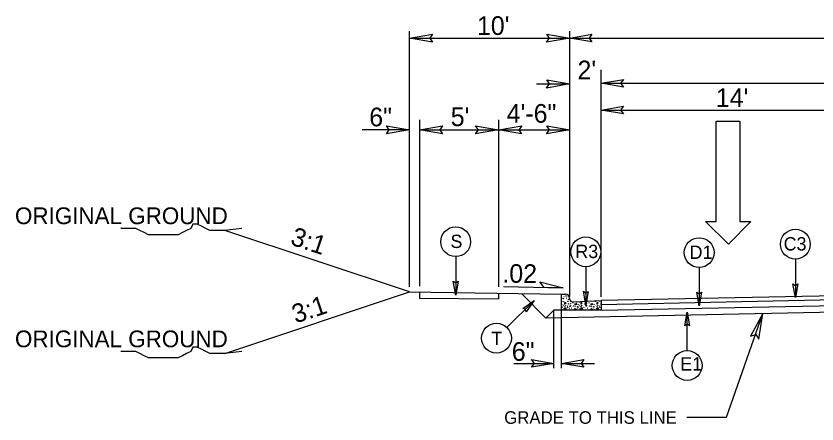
# Model space of a CAD drawing. Extents: x 958711 to 962106, y 831169 to 840840.
# Drawn here: x 960909.4 to 961244.1, y 838613.5 to 838784 of the extents above; entities that cross this region are included whole.
import ezdxf

# ---------------------------------------------------------------- set-up
doc = ezdxf.new("R2010")
doc.units = 0
for name, color, linetype in [('Old_Level_1', 7, 'Continuous'), ('Old_Level_11', 7, 'Continuous'), ('Old_Level_21', 7, 'Continuous'), ('Old_Level_3', 7, 'Continuous'), ('Prop Dimension Text', 7, 'Continuous'), ('Prop Lane Arrow CELL', 7, 'Continuous'), ('Typical ID Circle CELL', 7, 'Continuous'), ('Typical Terminator CELL', 7, 'Continuous'), ('Typical Text ID Circle CELL', 7, 'Continuous')]:
    doc.layers.add(name, color=color, linetype=linetype)

# ---------------------------------------------------------------- blocks, each defined once
blk = doc.blocks.new('Lane Arrow Through')
at = {"layer": 'Prop Lane Arrow CELL'}
for p, q in [((-3.15, 1.6), (-3.15, 3.1)), ((-3.15, 3.1), (0, 0)), ((-17.15, 1.6), (-3.15, 1.6)), ((-17.15, -1.7), (-17.15, 1.6)), ((0, 0), (-3.15, -3.2)), ((-3.15, -1.7), (-17.15, -1.7)), ((-3.15, -3.2), (-3.15, -1.7))]:
    blk.add_line(p, q, dxfattribs=at)

msp = doc.modelspace()

# ---------------------------------------------------------------- linework, layer by layer
at = {"layer": 'Old_Level_1'}
for p, q in [((961073.8, 838670.85), (961073.8, 838777.7)), ((961140.72, 838666.82), (961140.72, 838777.74)), ((961073.8, 838774.8), (961140.72, 838774.8)), ((961140.72, 838774.8), (961707.16, 838774.8)), ((961153.92, 838666.59), (961153.92, 838761.56)), ((961126.89, 838755.64), (961140.72, 838755.64)), ((961153.92, 838755.91), (961354.09, 838755.91)), ((961153.92, 838744.66), (961260.61, 838744.66)), ((961077.98, 838740.63), (961077.98, 838671.06)), ((961111, 838740.63), (961111, 838670.84)), ((961073.8, 838736.46), (961054.01, 838736.46)), ((961077.98, 838736.46), (961111, 838736.46)), ((961111, 838736.46), (961140.72, 838736.46)), ((961073.8, 838668.67), (960996.61, 838694.4)), ((961113.05, 838670.94), (961138.02, 838670.44)), ((960996.61, 838642.94), (961073.8, 838668.67)), ((961073.8, 838668.67), (961137.64, 838667.73)), ((961077.98, 838668.61), (961077.98, 838666.15)), ((961111, 838668.12), (961111, 838665.82)), ((961130.8, 838657.78), (961120.69, 838667.9)), ((961354.09, 838669.12), (961153.92, 838665.08)), ((961077.98, 838666.15), (961111, 838665.82)), ((961259.53, 838665.49), (961153.92, 838663.35)), ((961259.53, 838663.06), (961153.92, 838660.92)), ((961134.05, 838661.03), (961130.8, 838657.78)), ((961259.53, 838660.39), (961130.8, 838657.78)), ((961137.35, 838661.09), (961134.05, 838661.03)), ((961134.05, 838636.87), (961134.05, 838660.83)), ((961137.35, 838636.87), (961137.35, 838660.83)), ((961206.28, 838616.3), (961221.49, 838659.62)), ((961117.45, 838638.83), (961134.05, 838638.83)), ((961137.35, 838638.83), (961151.08, 838638.83)), ((961189.66, 838616.3), (961206.28, 838616.3))]:
    msp.add_line(p, q, dxfattribs=at)
at = {"layer": 'Old_Level_11'}
for p, q in [((961130.02, 838670.6), (961128.29, 838672.85)), ((961128.29, 838672.85), (961138.02, 838670.44)), ((961138.02, 838670.44), (961130.02, 838670.6))]:
    msp.add_line(p, q, dxfattribs=at)
for points in [[(961083.41, 838773.14), (961073.8, 838774.8), (961083.46, 838776.51), (961082.24, 838774.8)], [(961131.11, 838776.45), (961140.72, 838774.8), (961131.05, 838773.08), (961132.28, 838774.8)], [(961131.11, 838757.3), (961140.72, 838755.64), (961131.05, 838753.92), (961132.28, 838755.64)], [(961064.19, 838738.12), (961073.8, 838736.46), (961064.13, 838734.74), (961065.36, 838736.46)], [(961087.59, 838734.8), (961077.98, 838736.46), (961087.64, 838738.17), (961086.42, 838736.46)], [(961101.39, 838738.12), (961111, 838736.46), (961101.33, 838734.74), (961102.56, 838736.46)], [(961120.61, 838734.8), (961111, 838736.46), (961120.66, 838738.17), (961119.44, 838736.46)], [(961131.11, 838738.12), (961140.72, 838736.46), (961131.05, 838734.74), (961132.28, 838736.46)], [(961219.8, 838649.02), (961221.49, 838659.62), (961216.28, 838650.16), (961218.48, 838650.84)]]:
    msp.add_lwpolyline(points, close=True, dxfattribs=at)
at = {"layer": 'Old_Level_21'}
for points in [[(961003.71, 838695.28), (960996.61, 838694.4), (960994.84, 838694.4), (960992.18, 838694.4), (960990.4, 838694.4), (960988.63, 838695.28), (960986.85, 838696.18), (960985.08, 838697.06), (960983.31, 838697.06), (960982.41, 838695.28), (960980.65, 838694.4), (960978.87, 838693.51), (960977.1, 838692.63), (960975.32, 838692.63), (960973.55, 838692.63), (960971.78, 838692.63), (960970.01, 838692.63), (960968.23, 838692.63), (960966.46, 838692.63), (960964.68, 838692.63), (960962.91, 838693.51), (960961.14, 838694.4), (960959.37, 838695.28), (960956.7, 838695.28), (960954.93, 838695.28), (960953.15, 838695.28)], [(961003.71, 838643.82), (960996.61, 838642.94), (960994.84, 838642.94), (960992.18, 838642.94), (960990.4, 838642.94), (960988.63, 838643.82), (960986.85, 838644.72), (960985.08, 838645.6), (960983.31, 838645.6), (960982.41, 838643.82), (960980.65, 838642.94), (960978.87, 838642.04), (960977.1, 838641.17), (960975.32, 838641.17), (960973.55, 838641.17), (960971.78, 838641.17), (960970.01, 838641.17), (960968.23, 838641.17), (960966.46, 838641.17), (960964.68, 838641.17), (960962.91, 838642.04), (960961.14, 838642.94), (960959.37, 838643.82), (960956.7, 838643.82), (960954.93, 838643.82), (960953.15, 838643.82)]]:
    msp.add_lwpolyline(points, dxfattribs=at)
at = {"layer": 'Old_Level_3'}
for p, q in [((961137.35, 838664.41), (961137.35, 838667.44)), ((961137.64, 838667.73), (961139.01, 838667.73)), ((961137.35, 838661.09), (961137.35, 838664.41)), ((961138.62, 838664.18), (961138.62, 838663.6)), ((961139.21, 838664.15), (961138.62, 838664.18)), ((961138.62, 838663.6), (961139.21, 838664.15)), ((961140.8, 838665.68), (961140.69, 838665.54)), ((961140.69, 838665.54), (961140.84, 838665.57)), ((961142.38, 838664.5), (961153.92, 838665.08)), ((961142.38, 838664.5), (961142.38, 838664.5)), ((961142.84, 838663.77), (961142.94, 838663.29)), ((961143.67, 838663.54), (961142.84, 838663.77)), ((961142.94, 838663.29), (961143.67, 838663.54)), ((961145.35, 838664.18), (961145.35, 838663.6)), ((961145.94, 838664.15), (961145.35, 838664.18)), ((961145.35, 838663.6), (961145.94, 838664.15)), ((961149.57, 838663.77), (961149.67, 838663.29)), ((961150.4, 838663.54), (961149.57, 838663.77)), ((961149.67, 838663.29), (961150.4, 838663.54)), ((961152.09, 838664.18), (961152.09, 838663.6)), ((961152.67, 838664.15), (961152.09, 838664.18)), ((961152.09, 838663.6), (961152.67, 838664.15)), ((961153.92, 838665.08), (961153.92, 838661.09)), ((961153.92, 838661.09), (961137.35, 838661.09)), ((961138.54, 838661.48), (961139, 838662.13)), ((961139.17, 838661.51), (961138.54, 838661.48)), ((961139, 838662.13), (961139.17, 838661.51)), ((961142.65, 838661.21), (961142.99, 838661.82)), ((961143.55, 838661.42), (961142.65, 838661.21)), ((961142.99, 838661.82), (961143.55, 838661.42)), ((961145.27, 838661.48), (961145.73, 838662.13)), ((961145.91, 838661.51), (961145.27, 838661.48)), ((961145.73, 838662.13), (961145.91, 838661.51)), ((961149.38, 838661.21), (961149.72, 838661.82)), ((961150.28, 838661.42), (961149.38, 838661.21)), ((961149.72, 838661.82), (961150.28, 838661.42)), ((961151.99, 838661.48), (961152.45, 838662.13)), ((961152.64, 838661.51), (961151.99, 838661.48)), ((961152.45, 838662.13), (961152.64, 838661.51))]:
    msp.add_line(p, q, dxfattribs=at)
for centre in [(961138.32, 838666.64), (961139.18, 838667.01), (961140.29, 838666.89), (961137.41, 838666), (961137.5, 838663.41), (961138.05, 838664.61), (961138.17, 838665.9), (961138.2, 838663.01), (961138.97, 838663.1), (961139.34, 838666.09), (961139.98, 838664.8), (961140.26, 838663.69), (961140.32, 838665.59), (961140.97, 838662.95), (961141, 838663.75), (961141.09, 838664.76), (961142.07, 838664.15), (961143.52, 838664), (961144.23, 838663.41), (961144.93, 838663.01), (961145.7, 838663.1), (961146.99, 838663.69), (961147.7, 838662.95), (961147.73, 838663.75), (961148.8, 838664.15), (961150.25, 838664), (961150.96, 838663.41), (961151.5, 838664.61), (961151.66, 838663.01), (961152.42, 838663.1), (961153.44, 838664.8), (961153.72, 838663.69), (961137.53, 838661.23), (961137.61, 838662.34), (961138.05, 838661.48), (961138.72, 838662.56), (961139.77, 838662.77), (961139.92, 838662.22), (961140.72, 838661.76), (961140.87, 838662.68), (961141.4, 838661.91), (961142.35, 838662.8), (961143, 838662.53), (961143.95, 838662), (961144.04, 838662.53), (961144.26, 838661.23), (961144.34, 838662.34), (961144.77, 838661.48), (961145.45, 838662.56), (961146.5, 838662.77), (961146.65, 838662.22), (961147.45, 838661.76), (961147.6, 838662.68), (961148.13, 838661.91), (961149.08, 838662.8), (961149.73, 838662.53), (961150.68, 838662), (961150.77, 838662.53), (961150.99, 838661.23), (961151.07, 838662.34), (961151.5, 838661.48), (961152.18, 838662.56), (961153.22, 838662.77), (961153.38, 838662.22)]:
    msp.add_circle(centre, 0.0432, dxfattribs=at)
for centre, radius, start, end in [((961137.64, 838667.44), 0.287, 90, 180), ((961137.53, 838667.66), 0.0432, 259.6531, 10.3469), ((961139.01, 838666.07), 1.66, 1.0734, 90), ((961142.3, 838666.14), 1.64, 181.0734, 272.8624), ((961144.77, 838664.61), 0.0432, 167.7795, 17.938), ((961147.82, 838664.76), 0.0432, 169.8374, 15.8801), ((961137.31, 838662.53), 0.0432, 330.4173, 29.5827)]:
    msp.add_arc(centre, radius, start, end, dxfattribs=at)
at = {"layer": 'Typical ID Circle CELL'}
for p, q in [((961093.08, 838683.46), (961093.08, 838667.38)), ((961235.02, 838682.44), (961235.02, 838666.35)), ((961147.47, 838679.26), (961147.47, 838663.17)), ((961194.83, 838678.91), (961194.83, 838662.82)), ((961114.51, 838653.76), (961125.88, 838665.14)), ((961189.82, 838644.17), (961189.82, 838660.26))]:
    msp.add_line(p, q, dxfattribs=at)
for centre in [(961093.08, 838689.69), (961235.02, 838688.66), (961147.47, 838685.48), (961194.83, 838685.13), (961110.11, 838649.36), (961189.82, 838637.95)]:
    msp.add_circle(centre, 6.23, dxfattribs=at)
at = {"layer": 'Typical Terminator CELL'}
for points in [[(961149.94, 838773.21), (961140.72, 838774.8), (961149.99, 838776.44), (961148.81, 838774.8)], [(961163.15, 838754.32), (961153.92, 838755.91), (961163.2, 838757.55), (961162.02, 838755.91)], [(961163.15, 838743.08), (961153.92, 838744.66), (961163.2, 838746.3), (961162.02, 838744.66)], [(961094.07, 838673.14), (961093.08, 838667.38), (961092.06, 838673.17), (961093.08, 838672.44)], [(961236.02, 838672.11), (961235.02, 838666.35), (961234, 838672.14), (961235.02, 838671.41)], [(961148.47, 838668.94), (961147.47, 838663.17), (961146.45, 838668.97), (961147.47, 838668.23)], [(961195.82, 838668.59), (961194.83, 838662.82), (961193.81, 838668.62), (961194.83, 838667.88)], [(961121.11, 838661.76), (961125.88, 838665.14), (961122.51, 838660.31), (961122.31, 838661.56)], [(961188.83, 838654.5), (961189.82, 838660.26), (961190.84, 838654.46), (961189.82, 838655.2)], [(961124.83, 838640.42), (961134.05, 838638.83), (961124.77, 838637.19), (961125.95, 838638.83)], [(961146.57, 838637.24), (961137.35, 838638.83), (961146.62, 838640.47), (961145.45, 838638.83)]]:
    msp.add_lwpolyline(points, close=True, dxfattribs=at)

# ---------------------------------------------------------------- block references
at = {"layer": 'Old_Level_1', "xscale": 3, "yscale": 3, "rotation": -90.00000000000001}
msp.add_blockref('Lane Arrow Through', (961207.08, 838688.69), dxfattribs=at)

# ---------------------------------------------------------------- texts
at = {"layer": 'Old_Level_1'}
msp.add_text('GRADE TO THIS LINE', height=5.2473, dxfattribs=at).set_placement((961113.35, 838613.57))
at = {"layer": 'Old_Level_21'}
for p in [(960908.93, 838697.03), (960908.93, 838645.57)]:
    msp.add_text('ORIGINAL GROUND', height=7, dxfattribs=at).set_placement(p)
at = {"layer": 'Old_Level_3'}
for s, p in [("10'", (961101.97, 838776.12)), ("2'", (961143.99, 838757.59)), ('4\'-6"', (961114.39, 838739.43)), ('6"', (961056.96, 838737.93)), ("5'", (961091, 838738.02))]:
    msp.add_text(s, height=7.801, dxfattribs=at).set_placement(p)
for s, rotation, p in [('3:1', 341.5652, (961023.61, 838688.63)), ('.02', 359.4336, (961112.55, 838672.56)), ('3:1', 18.4348, (961026.2, 838655.46))]:
    msp.add_text(s, height=7.801, rotation=rotation, dxfattribs=at).set_placement(p)
at = {"layer": 'Prop Dimension Text'}
for s, p in [("14'", (961201.78, 838746.02)), ('6"', (961116.53, 838639.91))]:
    msp.add_text(s, height=7.801, rotation=0, dxfattribs=at).set_placement(p)
at = {"layer": 'Typical Text ID Circle CELL'}
for s, height, p in [('S', 5.57, (961090.91, 838687.06)), ('C3', 5.572, (961230.13, 838686.03)), ('R3', 5.572, (961143.09, 838682.85)), ('D1', 5.572, (961190.84, 838682.5)), ('E1', 5.572, (961186.93, 838635.81))]:
    msp.add_text(s, height=height, dxfattribs=at).set_placement(p)
msp.add_text('T', height=5.57, rotation=360, dxfattribs=at).set_placement((961107.96, 838646.46))

doc.saveas('drawing.dxf')
